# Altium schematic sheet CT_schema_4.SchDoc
size 309 x 315 mm
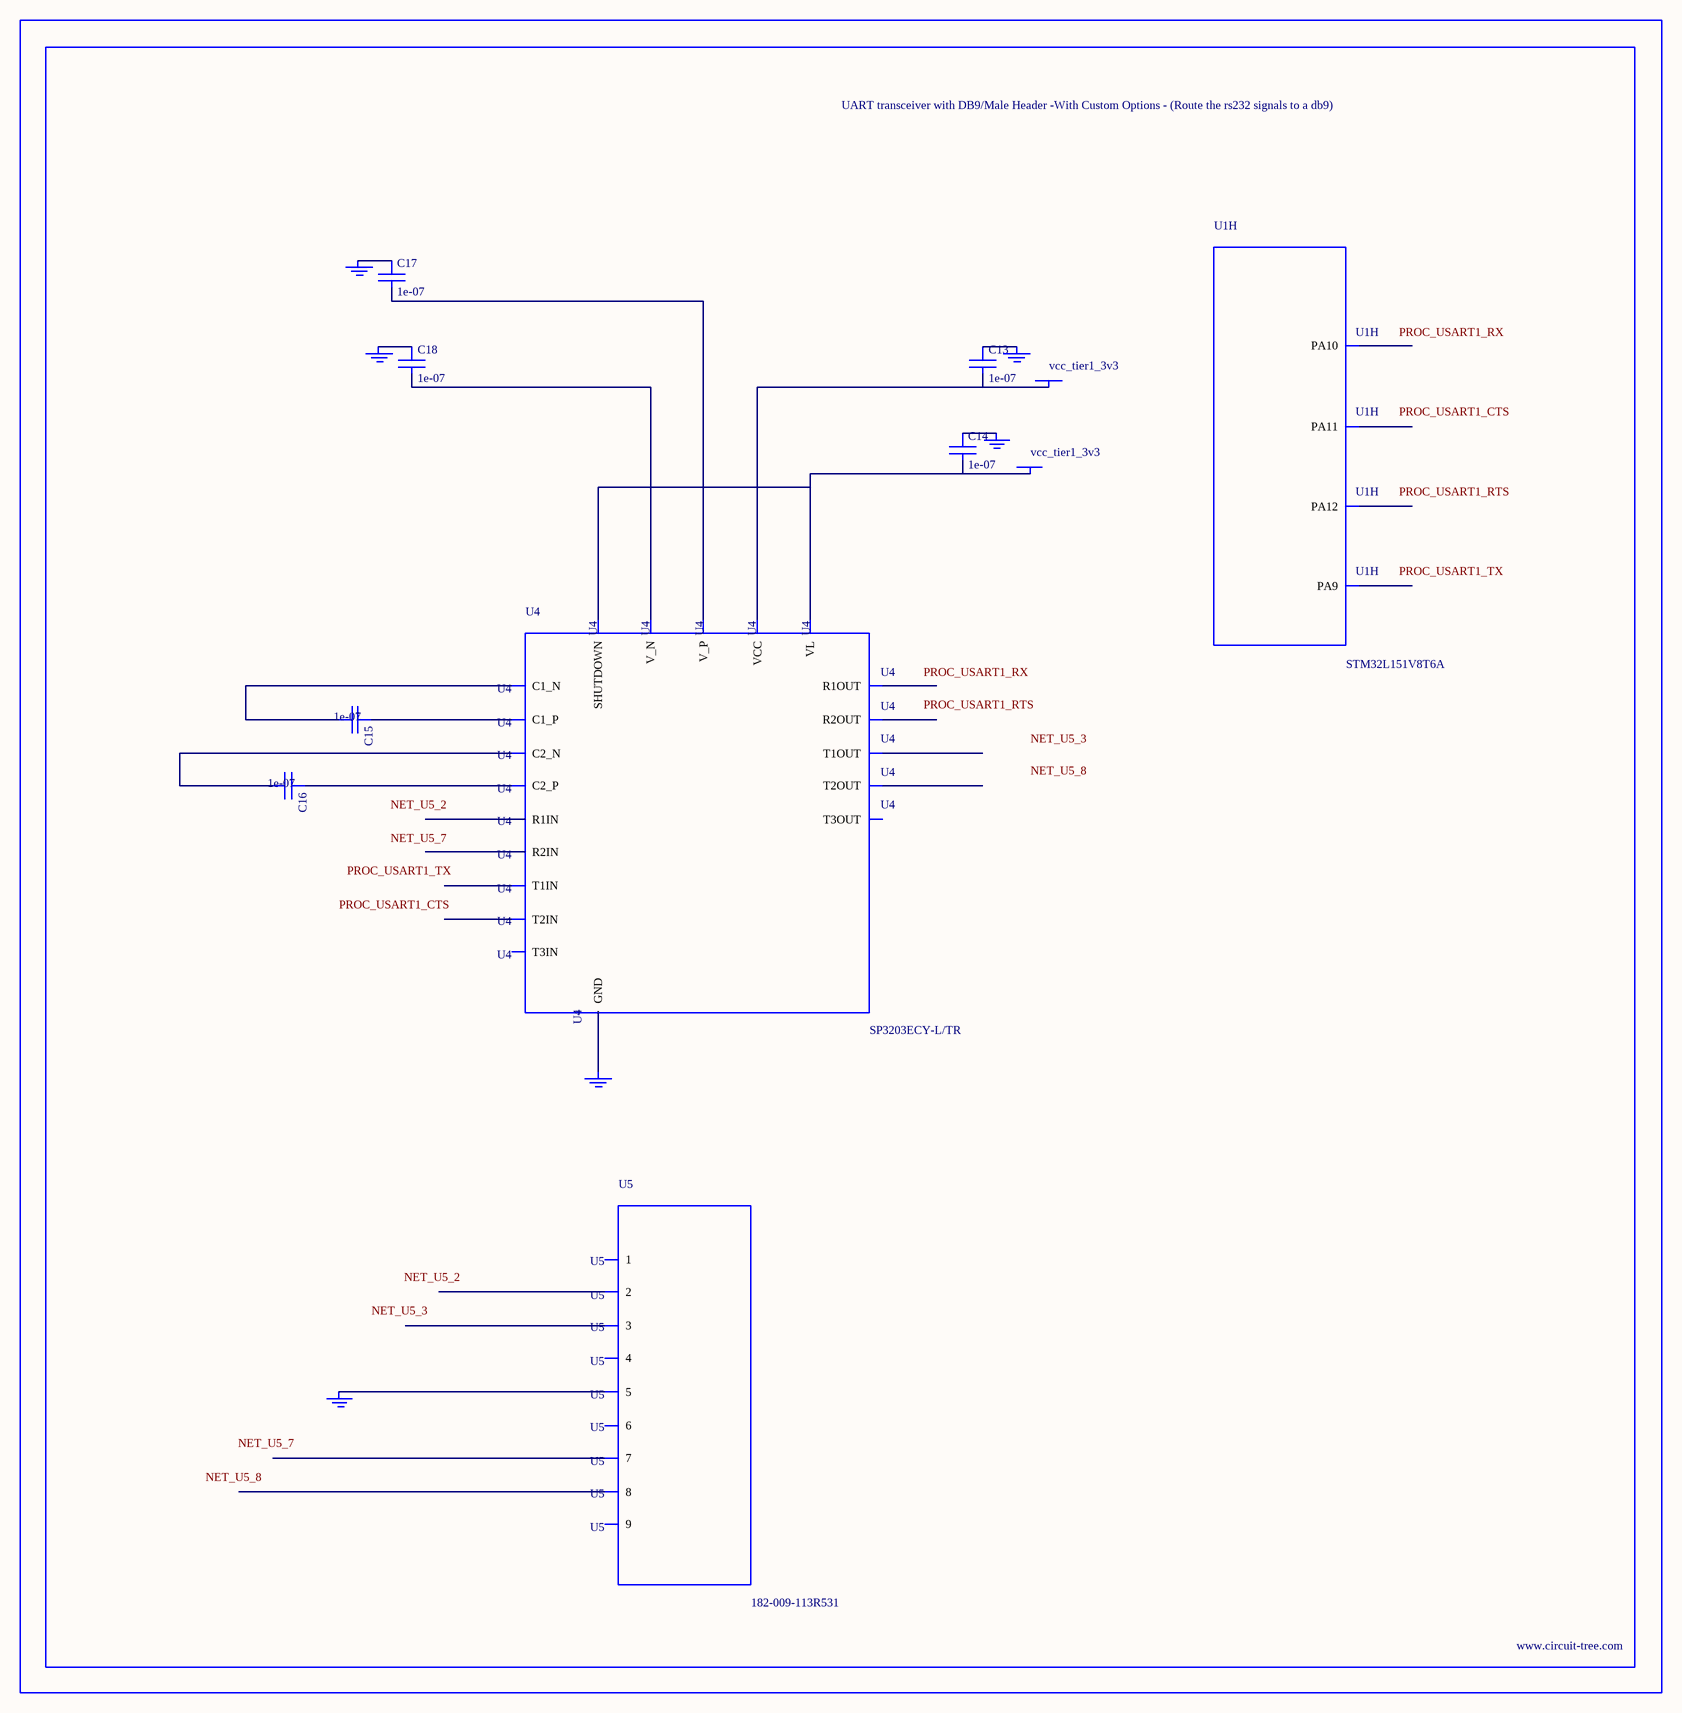
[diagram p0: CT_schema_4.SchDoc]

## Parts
BORDER3  (no value)
C13  1e-07  [C0402]
C14  1e-07  [C0402]
C15  1e-07  [C0402]
C16  1e-07  [C0402]
C17  1e-07  [C0402]
C18  1e-07  [C0402]
GND_INSTANCE_3_0  (no value)
GND_INSTANCE_3_1  (no value)
GND_INSTANCE_3_2  (no value)
GND_INSTANCE_3_3  (no value)
GND_INSTANCE_3_4  (no value)
GND_INSTANCE_3_5  (no value)
POWER_INSTANCE_3_0  vcc_tier1_3v3
POWER_INSTANCE_3_1  vcc_tier1_3v3
U1  STM32L151V8T6A  [LQFP100]  (part H of 9)
U4  SP3203ECY-L/TR  [TSSOP20-I]
U5  182-009-113R531  [182-009-MALE]

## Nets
NetC13_1: C13.1 GND_INSTANCE_3_3.0(GND)
NetC13_2: C13.2 POWER_INSTANCE_3_1.0(PWR) U4.19(VCC)
NetC14_1: C14.1 GND_INSTANCE_3_2.0(GND)
NetC14_2: C14.2 POWER_INSTANCE_3_0.0(PWR) U4.12(VL) U4.20(SHUTDOWN)
NetC15_1: C15.1 U4.1(C1_P)
NetC15_2: C15.2 U4.3(C1_N)
NetC16_1: C16.1 U4.4(C2_P)
NetC16_2: C16.2 U4.5(C2_N)
NetC17_1: C17.1 GND_INSTANCE_3_0.0(GND)
NetC17_2: C17.2 U4.2(V_P)
NetC18_1: C18.1 GND_INSTANCE_3_1.0(GND)
NetC18_2: C18.2 U4.6(V_N)
NetGND_INSTANCE_3_4_0: GND_INSTANCE_3_4.0(GND) U4.18(GND)
NetGND_INSTANCE_3_5_0: GND_INSTANCE_3_5.0(GND) U5.5

Not connected (* = marked no-connect by the designer): U1 68(PA9) 69(PA10) 70(PA11) 71(PA12); U4 7(T1IN) 8(T2IN) 9(T3IN) 10(R2OUT) 11(R1OUT) 13(R2IN) 14(R1IN) 15(T3OUT) 16(T2OUT) 17(T1OUT); U5 1 2 3 4 6 7 8 9

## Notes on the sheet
- Labels drawn without touching a wire or pin: NET_U5_2, NET_U5_3, NET_U5_7, NET_U5_8, PROC_USART1_CTS, PROC_USART1_RTS, PROC_USART1_RX, PROC_USART1_TX

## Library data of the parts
BORDER3 = BORDER_PAGE3
C13-C18 = C0402C104K3RACTU
GND_INSTANCE_3_0-GND_INSTANCE_3_5 = GND
POWER_INSTANCE_3_0 POWER_INSTANCE_3_1 = PWR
